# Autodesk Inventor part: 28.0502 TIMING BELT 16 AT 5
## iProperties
Created: 2007-06
Part Number: 28.0502 TIMING BELT 16 AT 5
Document SubType Name: Modeling
Designer: Andy Moles
Material: UHMW, White
Density: 0.94 g/cm^3
Author: Andy Moles
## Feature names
1. Extrusion1
2. NUMBER OF TEETH [Rectangular Pattern]
